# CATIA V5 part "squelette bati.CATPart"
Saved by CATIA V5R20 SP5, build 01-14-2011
Part number: squelette bati
Property "LENGTH": 0 mm
Property "Avert": 0 mm
Property "Ahori": 0 mm
Publications: "angleE", "plan profil", "Point.1", "Point.2", "plan dessous", "Point.14", "Droite.4", "Droite.5", "Avert", "Ahoriz", "Droite.6"
Bounding box of the stored display mesh (mm): x -1453 to 10078, y 0 to 3039.842, z -86.054 to 1485.26
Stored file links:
  F:\iao fini\squelette bati.CATPart
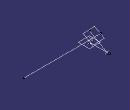
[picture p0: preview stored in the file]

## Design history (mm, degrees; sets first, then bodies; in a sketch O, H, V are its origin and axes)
Parameters
  angleE = -30 deg
  Avert = 550 mm
  Ahoriz = 280 mm
Point1: type OnPlane, Support Plane1, H 0, V 0, Direction (0, 1, 0)
Point2 "A": type OnPlane, Support Plane1, H 280 {= Ahoriz}, V 550 {= Avert}, Direction (0, 1, 0)
Line1: type Angle, RefPoint Point3, Curve Line2, Support Plane1, Start 2970, End -218, Angle -30 {= angleE}
Set1
  Plane1 "plan profil": type Offset, RefPlane yz-plane, Offset 0
  Plane2 "plan dessous": type Offset, RefPlane xy-plane, Offset 0
  Point3: type OnPlane, Support Plane1, H 2609.856, V 21.395, Direction (0, 1, 0)
  Line2: type PtPt, FirstPoint Point3, SecondPoint Point1, Support Plane1, Start 430
  Plane3: type Angle, RefPlane Plane2, Direction Line1, Angle -30 {= angleE}
  Line3: type PtDir, RefPoint Point2, Direction Plane1, Start 10078, End -1453
Body1 (main body)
